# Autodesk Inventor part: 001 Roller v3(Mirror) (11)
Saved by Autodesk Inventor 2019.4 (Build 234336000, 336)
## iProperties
Created: 2020-06
Part Number: 001 Roller v3(Mirror) (11)
Material: Generic
Document SubType Name: Modeling
Designer: Administrator
Density: 1 g/cm^3
Appearance: Default
Title: 001 Roller v3(Mirror) (11)
Author: Administrator
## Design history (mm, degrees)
